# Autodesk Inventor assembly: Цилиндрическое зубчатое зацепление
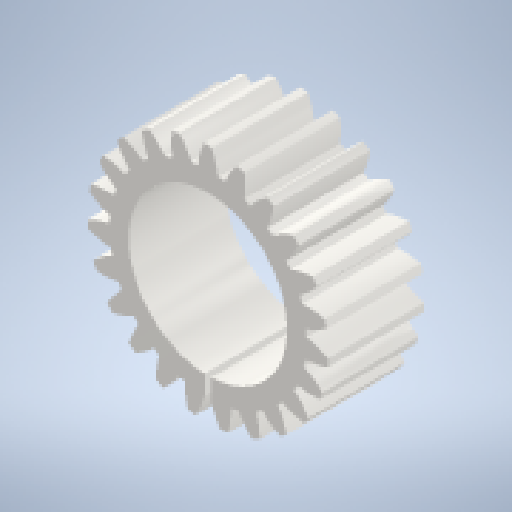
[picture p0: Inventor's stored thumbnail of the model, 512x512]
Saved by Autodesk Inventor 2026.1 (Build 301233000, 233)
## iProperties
ClientObjectVersion: 1
Created: 2026-01
Part Number: Цилиндрическое зубчатое зацепление
Document SubType Name: Assembly
Designer: Yury Melnikov
Categories: <?xml version="1.0" encoding="UTF-16"?> <MemberInstance><Categories><FamilyTemplate/><ParamToTemplateMap><ParamToTemplate><ParamToTemplate CategoryParameter="//
Author: Yury Melnikov
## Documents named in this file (3)
- C:\Users\user\Documents\Проекты\ВсОШ_РОБО\Робот\Сборка1\Мастер проектирования\Цилиндрическое зубчатое зацепление1.iam
- C:\Users\user\Documents\Проекты\ВсОШ_РОБО\Робот\Сборка1\Мастер проектирования\Цилиндрическое зубчатое зацепление11.ipt
- C:\Users\user\Documents\Проекты\ВсОШ_РОБО\Робот\Сборка1\Мастер проектирования\Цилиндрическое зубчатое зацепление21.ipt
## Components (2 placed, 2 different names)
1. Цилиндрическое зубчатое зацепление1:1 — ЗубчПер:1
2. Цилиндрическое зубчатое зацепление2:1 — ЗубчПер:1
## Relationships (1: RelateRotation 1)
- ЗубчПер:1 [RelateRotation]: Цилиндрическое зубчатое зацепление1:1 ↔ Цилиндрическое зубчатое зацепление2:1
